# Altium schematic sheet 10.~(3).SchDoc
size 420 x 297 mm
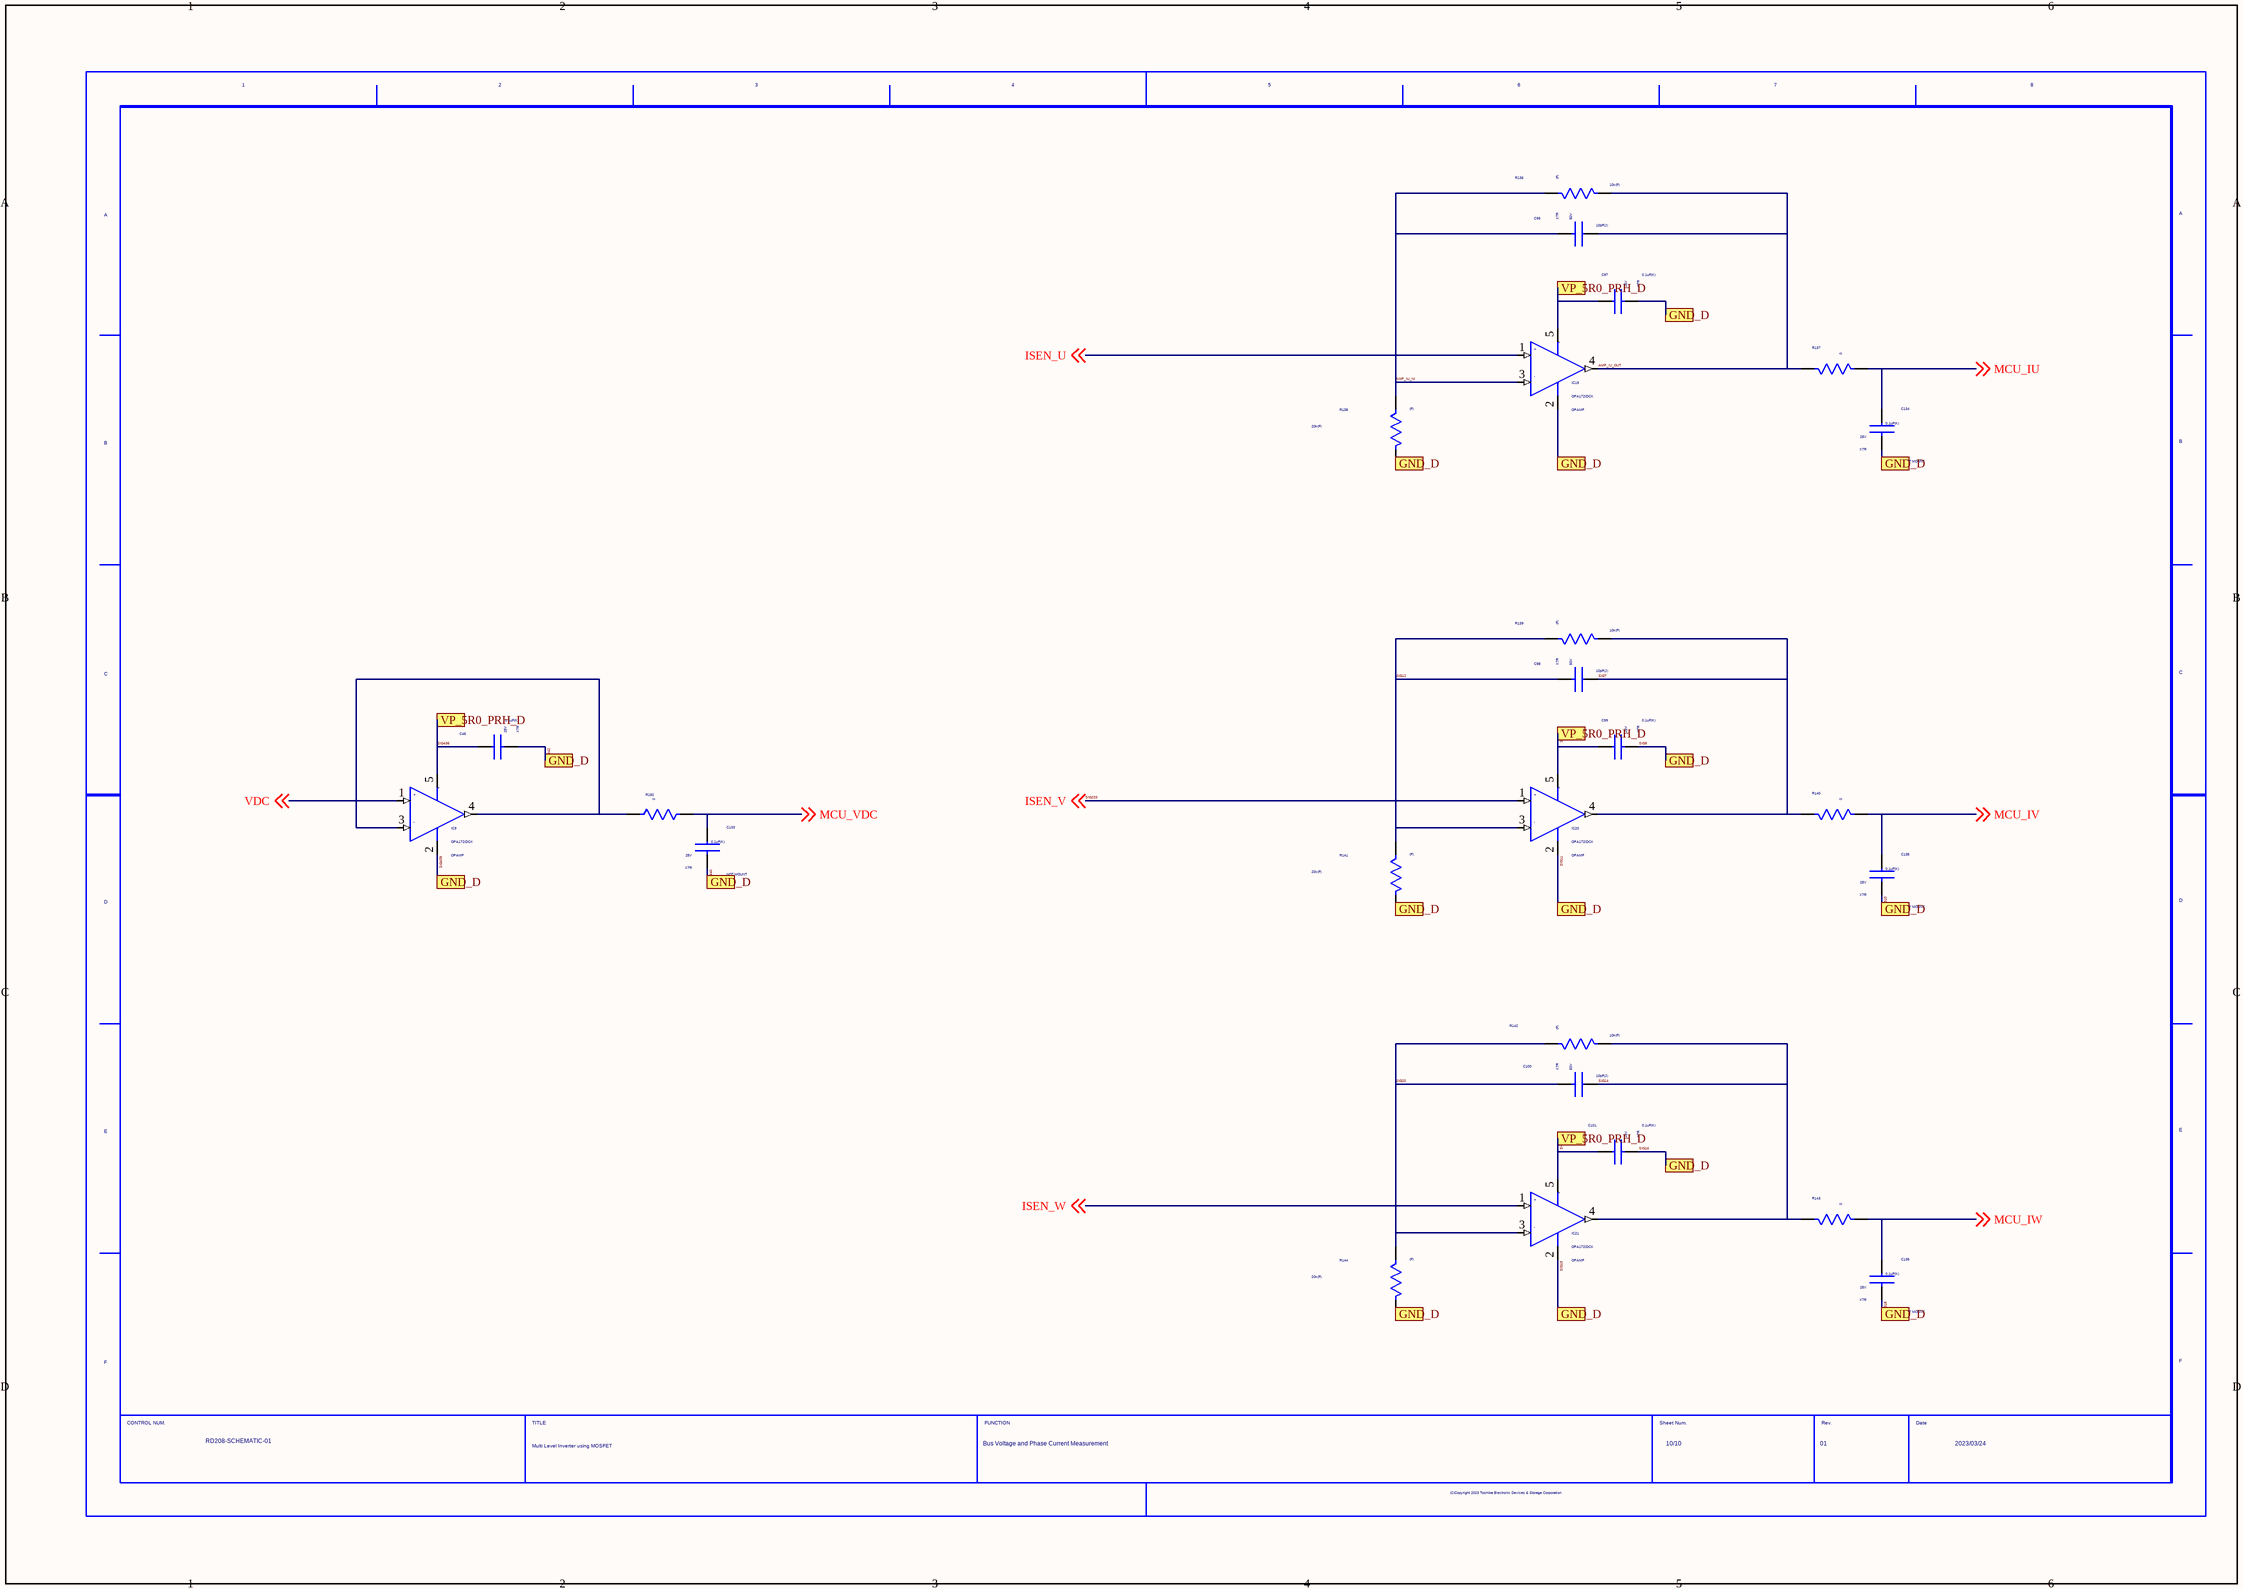
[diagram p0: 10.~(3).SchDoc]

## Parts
C45  VAL2: 25V  VALUE4: X7R  VAL1: 0.1uF(K)  (hidden comment: GRM155R71E104KE14D)
C96  VAL2: 50V  VALUE4: X7R  VAL1: 10pF(J)  (hidden comment: GRM1555C1H100RA01D)
C97  VAL2: 25V  VALUE4: X7R  VAL1: 0.1uF(K)  (hidden comment: GRM155R71E104KE14D)
C98  VAL2: 50V  VALUE4: X7R  VAL1: 10pF(J)  (hidden comment: GRM1555C1H100RA01D)
C99  VAL2: 25V  VALUE4: X7R  VAL1: 0.1uF(K)  (hidden comment: GRM155R71E104KE14D)
C100  VAL2: 50V  VALUE4: X7R  VAL1: 10pF(J)  (hidden comment: GRM1555C1H100RA01D)
C101  VAL2: 25V  VALUE4: X7R  VAL1: 0.1uF(K)  (hidden comment: GRM155R71E104KE14D)
C133  VAL2: 25V  VALUE4: X7R  VAL1: 0.1uF(K)  NOTMOUNT: NOT MOUNT  (hidden comment: GRM155R71E104KE14D)
C134  VAL2: 25V  VALUE4: X7R  VAL1: 0.1uF(K)  NOTMOUNT: NOT MOUNT  (hidden comment: GRM155R71E104KE14D)
C135  VAL2: 25V  VALUE4: X7R  VAL1: 0.1uF(K)  NOTMOUNT: NOT MOUNT  (hidden comment: GRM155R71E104KE14D)
C136  VAL2: 25V  VALUE4: X7R  VAL1: 0.1uF(K)  NOTMOUNT: NOT MOUNT  (hidden comment: GRM155R71E104KE14D)
IC9  VAL2: OPAMP  VAL1: OPA172IDCK  (hidden comment: OPA172IDCKT)
IC19  VAL2: OPAMP  VAL1: OPA172IDCK  (hidden comment: OPA172IDCKT)
IC20  VAL2: OPAMP  VAL1: OPA172IDCK  (hidden comment: OPA172IDCKT)
IC21  VAL2: OPAMP  VAL1: OPA172IDCK  (hidden comment: OPA172IDCKT)
R136  VALUE4: (F)  VAL1: 10k(F)  (hidden comment: ERJ2RKF1002X)
R137  VAL1: 0  (hidden comment: ERJ2GE0R00X)
R138  VALUE4: (F)  VAL1: 20k(F)  (hidden comment: ERJ2RKF2002X)
R139  VALUE4: (F)  VAL1: 10k(F)  (hidden comment: ERJ2RKF1002X)
R140  VAL1: 0  (hidden comment: ERJ2GE0R00X)
R141  VALUE4: (F)  VAL1: 20k(F)  (hidden comment: ERJ2RKF2002X)
R142  VALUE4: (F)  VAL1: 10k(F)  (hidden comment: ERJ2RKF1002X)
R143  VAL1: 0  (hidden comment: ERJ2GE0R00X)
R144  VALUE4: (F)  VAL1: 20k(F)  (hidden comment: ERJ2RKF2002X)
R192  VAL1: 0  (hidden comment: ERJ2GE0R00X)
U?  DATE: 2023/03/24  TITLE: Multi Level Inverter using MOSFET  REVISION: 01  SHEETNUMBER: 10/10  DRAWINGNUMBER: RD208-SCHEMATIC-01  FUNCTION: Bus Voltage and Phase Current Measurement  (hidden comment: WAKU_DEF100)

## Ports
GND_D, VP_5R0_PRH_D

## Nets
AMP_IU_NI: C96.2 IC19.3(-IN) R136.2 R138.2
AMP_IU_OUT: C96.1 IC19.4(OUT) R136.1 R137.2
ISEN_U: IC19.1(+IN) ; off-sheet ISEN_U
ISEN_W: IC21.1(+IN) ; off-sheet ISEN_W
MCU_IU: C134.1 R137.1 ; off-sheet MCU_IU
MCU_IV: C135.1 R140.1 ; off-sheet MCU_IV
MCU_IW: C136.1 R143.1 ; off-sheet MCU_IW
MCU_VDC: C133.1 R192.2 ; off-sheet MCU_VDC
SIG7: C98.1 IC20.4(OUT) R139.1 R140.2
SIG10: C45.2 C97.2 C99.2 C101.2 C133.2 C134.2 C135.2 C136.2 IC9.2(-V) IC19.2(-V) IC20.2(-V) IC21.2(-V) R138.1 R141.1 R144.1 ; port GND_D  [also labelled SIG11, SIG16, SIG18, SIG19, SIG439, SIG440, SIG442, SIG9]
SIG12: C98.2 IC20.3(-IN) R139.2 R141.2
SIG14: C100.1 IC21.4(OUT) R142.1 R143.2
SIG15: C45.1 C97.1 C99.1 C101.1 IC9.5(+V) IC19.5(+V) IC20.5(+V) IC21.5(+V) ; port VP_5R0_PRH_D  [also labelled SIG436, SIG8]
SIG20: C100.2 IC21.3(-IN) R142.2 R144.2
SIG233: IC20.1(+IN) ; off-sheet ISEN_V  [also labelled ISEN_V]
SIG438: IC9.3(-IN) IC9.4(OUT) R192.1
VDC: IC9.1(+IN) ; off-sheet VDC

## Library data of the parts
C45 = GRM155R71E104KE14D: MANUFACTURER: MURATA; ITEM: CAP Ceramic; SIZECODESMD: 1005; TIME: 08:44:45; UPDATEUSER: t5459927; SAVECOUNT: 1; OriginalSymbolOrigin: (0,0); INSTANCENAME: INS15923208
C96 C98 C100 = GRM1555C1H100RA01D: MANUFACTURER: MURATA; ITEM: CAP Ceramic; SIZECODESMD: 1005; TIME: 08:44:45; UPDATEUSER: t5459927; SAVECOUNT: 1; OriginalSymbolOrigin: (0,0); INSTANCENAME: INS15880882
C97 C99 C101 = GRM155R71E104KE14D: MANUFACTURER: MURATA; ITEM: CAP Ceramic; SIZECODESMD: 1005; TIME: 08:44:45; UPDATEUSER: t5459927; SAVECOUNT: 1; OriginalSymbolOrigin: (0,0); INSTANCENAME: INS15883585
C133 = GRM155R71E104KE14D: MANUFACTURER: MURATA; ITEM: CAP Ceramic; SIZECODESMD: 1005; TIME: 08:44:45; UPDATEUSER: t5459927; SAVECOUNT: 1; OriginalSymbolOrigin: (0,0); INSTANCENAME: INS17202360
C134-C136 = GRM155R71E104KE14D: MANUFACTURER: MURATA; ITEM: CAP Ceramic; SIZECODESMD: 1005; TIME: 08:44:45; UPDATEUSER: t5459927; SAVECOUNT: 1; OriginalSymbolOrigin: (0,0); INSTANCENAME: INS17202303
IC9 = OPA172IDCKT: MANUFACTURER: TI; ITEM: Operational Amplifier; ORDER: 0; TIME: 08:44:45; UPDATEUSER: t5459927; SAVECOUNT: 1; OriginalSymbolOrigin: (0,0); INSTANCENAME: INS16694428
IC19-IC21 = OPA172IDCKT: MANUFACTURER: TI; ITEM: Operational Amplifier; ORDER: 0; TIME: 08:44:45; UPDATEUSER: t5459927; SAVECOUNT: 1; OriginalSymbolOrigin: (0,0); INSTANCENAME: INS16693220
R136 R139 R142 = ERJ2RKF1002X: MANUFACTURER: Panasonic; ITEM: Register; VAL2: 100mW; SIZECODESMD: 1005; TIME: 08:44:45; UPDATEUSER: t5459927; SAVECOUNT: 1; OriginalSymbolOrigin: (0,0); INSTANCENAME: INS16030382
R137 R140 R143 = ERJ2GE0R00X: MANUFACTURER: Panasonic; ITEM: Register; VAL2: 1/10W; SIZECODESMD: 1005; TIME: 08:44:45; UPDATEUSER: t5459927; SAVECOUNT: 1; OriginalSymbolOrigin: (0,0); INSTANCENAME: INS17202155
R138 R141 R144 = ERJ2RKF2002X: MANUFACTURER: Panasonic; ITEM: Register; VAL2: 100mW; SIZECODESMD: 1005; TIME: 08:44:45; UPDATEUSER: t5459927; SAVECOUNT: 1; OriginalSymbolOrigin: (0,0); INSTANCENAME: INS16030446
R192 = ERJ2GE0R00X: MANUFACTURER: Panasonic; ITEM: Register; VAL2: 1/10W; SIZECODESMD: 1005; TIME: 08:44:45; UPDATEUSER: t5459927; SAVECOUNT: 1; OriginalSymbolOrigin: (0,0); INSTANCENAME: INS16109810
U? = WAKU_DEF100: PLOTTIME: HH:MM; SAVEAREA0: 185750,-43960,448537,75779; TIME: 14:30:25; UPDATEUSER: PS4_common_PC; UPDATETIME: 08:26:28; SAVECOUNT: 8; OriginalSymbolOrigin: (10160,284480)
